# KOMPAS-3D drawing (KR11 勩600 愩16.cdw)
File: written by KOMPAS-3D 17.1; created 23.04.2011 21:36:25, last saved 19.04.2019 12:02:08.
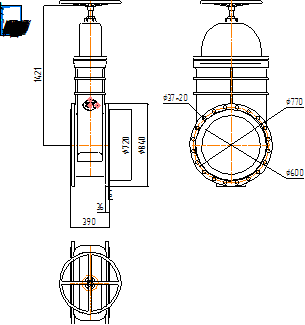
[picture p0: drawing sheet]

Sheet 1: A4, portrait

Title block, sheet 1: name: KR11 Ду600 Ру16; material: Внимание! Данный продукт является объектом авторского права ООО «Торговый Дом АДЛ». / Запрещается изменение, копирование, распространение / (в том числе путем копирования на другие сайты и ресурсы в Интернете) / или любое иное использование информации и объектов без предварительного / согласия правообладателя (ООО «Торговый Дом АДЛ»).; scale: 1:1; sheets: 1; organisation: ООО "Торговый дом АДЛ"; sheet format: A4; stored path: \\adlc.lan\data\АДЛ_ПКД\3D-модели\ADL production\Клиновые задвижки серии KR ГРАНАР\Клиновые задвижки KR11\KOMPAS 2D\KR11 Ду600 Ру16.cdw

Views: Спереди 4, Проекционный вид 5
Dimensions and other numbers on the sheet: 840; 720; 1421; 390; 36; 5; 1:1; 1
